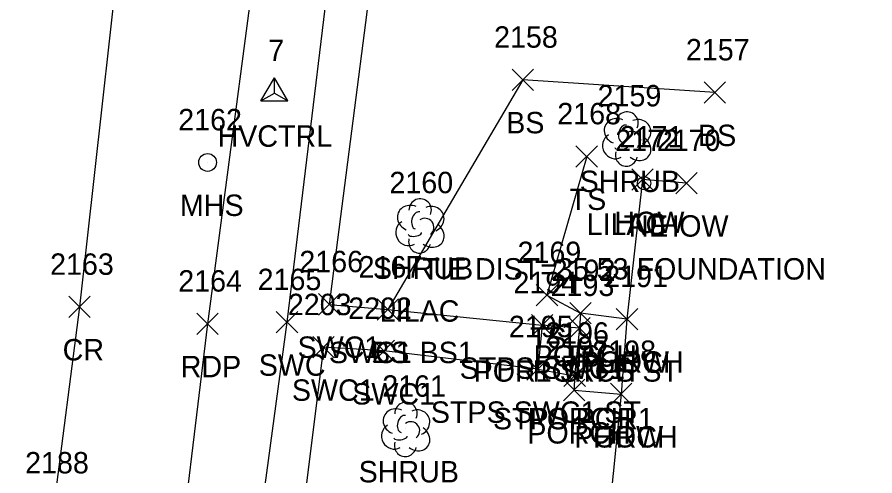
# Model space of a CAD drawing. Extents: x 1651305 to 1654558, y 539481 to 548441.
# Drawn here: x 1654363.2 to 1654443.3, y 544215.2 to 544258.1 of the extents above; entities that cross this region are included whole.
import ezdxf

# ---------------------------------------------------------------- set-up
doc = ezdxf.new("R2010")
doc.units = 0
for name, color, linetype in [('C_A', 7, 'Continuous'), ('C_C', 7, 'Continuous'), ('C_I', 7, 'Continuous'), ('CBP', 7, 'Continuous'), ('CPSM', 7, 'Continuous'), ('L_A', 7, 'Continuous'), ('L_C', 7, 'Continuous'), ('L_I', 7, 'Continuous'), ('L_TIC', 7, 'Continuous'), ('LBC', 7, 'Continuous'), ('LBF', 7, 'Continuous'), ('LELB', 7, 'Continuous'), ('LSH', 7, 'Continuous'), ('P_A', 7, 'Continuous'), ('P_I', 7, 'Continuous'), ('P_TIC', 7, 'Continuous'), ('PET', 7, 'Continuous'), ('PRC', 7, 'Continuous'), ('R_A', 7, 'Continuous'), ('R_I', 7, 'Continuous'), ('R_TIC', 7, 'Continuous'), ('RSW', 7, 'Continuous'), ('U_A', 7, 'Continuous'), ('U_I', 7, 'Continuous'), ('USMH', 7, 'Continuous')]:
    doc.layers.add(name, color=color, linetype=linetype)

msp = doc.modelspace()

# ---------------------------------------------------------------- linework, layer by layer
at = {"layer": 'CBP'}
for radius in [0.625, 0.0833]:
    msp.add_circle((1654421.726, 544242.57), radius, dxfattribs=at)
at = {"layer": 'CPSM'}
for p, q in [((1654385.957, 544250.252), (1654387.207, 544252.417)), ((1654388.457, 544250.252), (1654387.207, 544252.417)), ((1654387.208, 544250.973), (1654387.207, 544252.417)), ((1654385.957, 544250.252), (1654387.208, 544250.973)), ((1654387.208, 544250.973), (1654387.208, 544250.973)), ((1654387.208, 544250.973), (1654388.457, 544250.252)), ((1654385.957, 544250.252), (1654388.457, 544250.252))]:
    msp.add_line(p, q, dxfattribs=at)
at = {"layer": 'L_TIC'}
for points in [[(1654409.411, 544251.227), (1654411.411, 544253.227)], [(1654411.411, 544251.227), (1654409.411, 544253.227)], [(1654427.321, 544250.038), (1654429.321, 544252.038)], [(1654429.321, 544250.038), (1654427.321, 544252.038)], [(1654415.365, 544244.072), (1654417.365, 544246.072)], [(1654417.365, 544244.072), (1654415.365, 544246.072)], [(1654420.566, 544241.909), (1654422.566, 544243.909)], [(1654422.566, 544241.909), (1654420.566, 544243.909)], [(1654424.688, 544241.577), (1654426.688, 544243.577)], [(1654426.688, 544241.577), (1654424.688, 544243.577)], [(1654411.658, 544231.112), (1654413.658, 544233.112)], [(1654413.658, 544231.112), (1654411.658, 544233.112)], [(1654396.808, 544229.762), (1654398.808, 544231.762)], [(1654398.808, 544229.762), (1654396.808, 544231.762)], [(1654414.792, 544229.434), (1654416.792, 544231.434)], [(1654416.792, 544229.434), (1654414.792, 544231.434)], [(1654414.792, 544229.434), (1654416.792, 544231.434)], [(1654416.792, 544229.434), (1654414.792, 544231.434)], [(1654419.127, 544228.866), (1654421.127, 544230.866)], [(1654421.127, 544228.866), (1654419.127, 544230.866)], [(1654419.127, 544228.866), (1654421.127, 544230.866)], [(1654421.127, 544228.866), (1654419.127, 544230.866)], [(1654411.219, 544228.296), (1654413.219, 544230.296)], [(1654413.219, 544228.296), (1654411.219, 544230.296)], [(1654414.695, 544228.032), (1654416.695, 544230.032)], [(1654416.695, 544228.032), (1654414.695, 544230.032)], [(1654414.695, 544228.032), (1654416.695, 544230.032)], [(1654416.695, 544228.032), (1654414.695, 544230.032)], [(1654410.793, 544224.188), (1654412.793, 544226.188)], [(1654412.793, 544224.188), (1654410.793, 544226.188)], [(1654414.241, 544223.579), (1654416.241, 544225.579)], [(1654416.241, 544223.579), (1654414.241, 544225.579)], [(1654414.241, 544223.579), (1654416.241, 544225.579)], [(1654416.241, 544223.579), (1654414.241, 544225.579)], [(1654414.201, 544222.252), (1654416.201, 544224.252)], [(1654416.201, 544222.252), (1654414.201, 544224.252)], [(1654418.583, 544221.879), (1654420.583, 544223.879)], [(1654420.583, 544221.879), (1654418.583, 544223.879)], [(1654418.583, 544221.879), (1654420.583, 544223.879)], [(1654420.583, 544221.879), (1654418.583, 544223.879)]]:
    msp.add_lwpolyline(points, dxfattribs=at)
at = {"layer": 'LBC'}
msp.add_lwpolyline([(1654425.688, 544242.577), (1654421.566, 544242.909), (1654420.127, 544229.866), (1654419.583, 544222.879), (1654418.102, 544208.06), (1654421.917, 544207.562)], dxfattribs=at)
at = {"layer": 'LBF'}
for points in [[(1654420.127, 544229.866), (1654415.792, 544230.434), (1654415.695, 544229.032), (1654415.241, 544224.579), (1654415.201, 544223.252), (1654419.583, 544222.879)], [(1654415.695, 544229.032), (1654412.219, 544229.296), (1654411.793, 544225.188), (1654415.241, 544224.579)]]:
    msp.add_lwpolyline(points, dxfattribs=at)
at = {"layer": 'LELB'}
for points in [[(1654428.321, 544251.038), (1654410.411, 544252.227), (1654397.808, 544230.762)], [(1654416.365, 544245.072), (1654412.658, 544232.112), (1654415.792, 544230.434)]]:
    msp.add_lwpolyline(points, dxfattribs=at)
at = {"layer": 'LSH'}
for p, q in [((1654420.084, 544246.744), (1654420.084, 544246.744)), ((1654420.084, 544246.744), (1654420.084, 544246.744)), ((1654400.775, 544238.634), (1654400.775, 544238.634)), ((1654400.775, 544238.634), (1654400.775, 544238.634)), ((1654399.447, 544219.625), (1654399.447, 544219.625)), ((1654399.447, 544219.625), (1654399.447, 544219.625))]:
    msp.add_line(p, q, dxfattribs=at)
for centre in [(1654420.131, 544248.178), (1654400.822, 544240.068), (1654399.494, 544221.059)]:
    msp.add_arc(centre, 1.047, 335.52715, 180.95627, dxfattribs=at)
for centre, major_axis, ratio, start_param, end_param in [((1654419.292, 544247.411), (1.21, -0.512), 0.895232, 1.570796, 4.712389), ((1654419.875, 544247.202), (-0.208, -0.792), 0.645439, 3.141593, 6.283185), ((1654421.125, 544247.328), (-1.141, -0.483), 0.949671, 1.570796, 4.712389), ((1654420.584, 544246.577), (-0.5, 0.667), 0.989748, 3.141593, 6.283185), ((1654419.001, 544246.035), (0.584, -1.042), 0.959034, 3.141593, 6.283185), ((1654421.084, 544245.911), (-1.09, 0.792), 0.841452, 1.570796, 4.712389), ((1654419.626, 544245.994), (-0.625, -0.083), 0.423636, 0, 3.141593), ((1654420.084, 544245.244), (0.265, 1.061), 0.942809, 1.570796, 4.712389), ((1654399.984, 544239.3), (1.21, -0.512), 0.895232, 1.570796, 4.712389), ((1654401.817, 544239.217), (-1.141, -0.483), 0.949671, 1.570796, 4.712389), ((1654400.567, 544239.092), (-0.208, -0.792), 0.645439, 3.141593, 6.283185), ((1654401.275, 544238.467), (-0.5, 0.667), 0.989748, 3.141593, 6.283185), ((1654399.692, 544237.925), (0.584, -1.042), 0.959034, 3.141593, 6.283185), ((1654401.776, 544237.801), (-1.09, 0.792), 0.841452, 1.570796, 4.712389), ((1654400.317, 544237.884), (-0.625, -0.083), 0.423636, 0, 3.141593), ((1654400.776, 544237.134), (0.265, 1.061), 0.942809, 1.570796, 4.712389), ((1654398.655, 544220.292), (1.21, -0.512), 0.895232, 1.570796, 4.712389), ((1654399.238, 544220.084), (-0.208, -0.792), 0.645439, 3.141593, 6.283185), ((1654400.488, 544220.209), (-1.141, -0.483), 0.949671, 1.570796, 4.712389), ((1654399.947, 544219.459), (-0.5, 0.667), 0.989748, 3.141593, 6.283185), ((1654398.364, 544218.917), (0.584, -1.042), 0.959034, 3.141593, 6.283185), ((1654400.447, 544218.792), (-1.09, 0.792), 0.841452, 1.570796, 4.712389), ((1654398.989, 544218.875), (-0.625, -0.083), 0.423636, 0, 3.141593), ((1654399.447, 544218.125), (0.265, 1.061), 0.942809, 1.570796, 4.712389)]:
    msp.add_ellipse(centre, major_axis=major_axis, ratio=ratio, start_param=start_param, end_param=end_param, dxfattribs=at)
at = {"layer": 'P_TIC'}
for points in [[(1654368.008, 544230.012), (1654370.008, 544232.012)], [(1654370.008, 544230.012), (1654368.008, 544232.012)], [(1654379.974, 544228.445), (1654381.974, 544230.445)], [(1654381.974, 544228.445), (1654379.974, 544230.445)]]:
    msp.add_lwpolyline(points, dxfattribs=at)
at = {"layer": 'PET'}
msp.add_lwpolyline([(1654345.042, 544588.36), (1654350.59, 544607.191), (1654356.582, 544624.309), (1654366.692, 544597.705), (1654378.699, 544565.627), (1654388.798, 544536.019), (1654394.392, 544506.433), (1654399.121, 544481.008), (1654401.125, 544462.893), (1654401.531, 544436.346), (1654401.825, 544421.309), (1654397.366, 544359.696), (1654394.392, 544336.586), (1654391.404, 544308.963), (1654388.941, 544290.736), (1654386.845, 544274.06), (1654380.974, 544229.445), (1654377.749, 544202.908), (1654375.628, 544181.037), (1654372.192, 544149.754), (1654366.612, 544105.723), (1654362.798, 544072.788)], dxfattribs=at)
at = {"layer": 'PRC'}
msp.add_lwpolyline([(1654350.59, 544607.191), (1654355.931, 544592.699), (1654363.685, 544570.628), (1654372.223, 544542.272), (1654380.244, 544505.389), (1654384.95, 544473.916), (1654386.821, 544433.75), (1654385.713, 544395.522), (1654383.86, 544365.997), (1654380.919, 544339.646), (1654377.996, 544311.086), (1654373.889, 544274.842), (1654369.008, 544231.012), (1654366.63, 544212.463), (1654362.444, 544177.974), (1654359.488, 544151.886), (1654354.071, 544107.932), (1654348.42, 544063.008)], dxfattribs=at)
at = {"layer": 'R_TIC'}
for points in [[(1654391.335, 544230.256), (1654393.335, 544232.256)], [(1654393.335, 544230.256), (1654391.335, 544232.256)], [(1654396.808, 544229.762), (1654398.808, 544231.762)], [(1654398.808, 544229.762), (1654396.808, 544231.762)], [(1654387.386, 544228.583), (1654389.386, 544230.583)], [(1654389.386, 544228.583), (1654387.386, 544230.583)], [(1654411.219, 544228.296), (1654413.219, 544230.296)], [(1654413.219, 544228.296), (1654411.219, 544230.296)], [(1654390.804, 544226.245), (1654392.804, 544228.245)], [(1654392.804, 544226.245), (1654390.804, 544228.245)], [(1654396.438, 544225.898), (1654398.438, 544227.898)], [(1654398.438, 544225.898), (1654396.438, 544227.898)], [(1654410.793, 544224.188), (1654412.793, 544226.188)], [(1654412.793, 544224.188), (1654410.793, 544226.188)]]:
    msp.add_lwpolyline(points, dxfattribs=at)
at = {"layer": 'RSW'}
for points in [[(1654407.404, 544661.775), (1654407.293, 544658.868), (1654407.962, 544657.877), (1654443.269, 544654.592), (1654438.81, 544619.894), (1654433.558, 544580.17), (1654430.136, 544553.995), (1654428.025, 544537.281), (1654424.833, 544512.838), (1654419.77, 544473.615), (1654412.659, 544419.662), (1654404.122, 544354.774), (1654402.102, 544339.773), (1654395.487, 544286.058), (1654394.013, 544276.122), (1654388.386, 544229.583), (1654383.891, 544196.376), (1654382.201, 544184.333), (1654378.352, 544149.148), (1654372.361, 544105.495), (1654368.546, 544072.052)], [(1654433.769, 544447.317), (1654420.392, 544448.732), (1654416.298, 544419.47), (1654415.224, 544408.685), (1654412.657, 544388.617), (1654423.018, 544387.519), (1654429.579, 544386.827), (1654429.097, 544382.97), (1654422.687, 544383.714), (1654411.983, 544384.286), (1654408, 544354.107), (1654405.993, 544338.287), (1654403.211, 544318.213), (1654402.851, 544314.962), (1654399.432, 544285.106), (1654398.089, 544275.966), (1654392.335, 544231.256), (1654397.808, 544230.762), (1654412.219, 544229.296)], [(1654411.793, 544225.188), (1654397.438, 544226.898), (1654391.804, 544227.245), (1654387.757, 544194.912), (1654386.473, 544185.092), (1654381.826, 544148.772), (1654376.181, 544105.122), (1654374.342, 544091.887), (1654373.966, 544088.879), (1654371.749, 544071.943)]]:
    msp.add_lwpolyline(points, dxfattribs=at)
at = {"layer": 'USMH'}
for p, q in [((1654380.973, 544244.509), (1654380.973, 544244.509)), ((1654381.806, 544244.509), (1654381.806, 544244.509))]:
    msp.add_line(p, q, dxfattribs=at)
msp.add_circle((1654380.973, 544244.509), 0.833, dxfattribs=at)

# ---------------------------------------------------------------- texts
at = {"layer": 'C_A'}
for s, p in [('HVCTRL', (1654381.901, 544245.973)), ('TIE', (1654419.805, 544237.57))]:
    msp.add_text(s, height=2, dxfattribs=at).set_placement(p)
at = {"layer": 'C_C'}
msp.add_text('TIE DIST=35.53 FOUNDATION', height=2, dxfattribs=at).set_placement((1654401.026, 544233.57))
at = {"layer": 'C_I'}
for s, p in [('7', (1654386.641, 544253.973)), ('2172', (1654419.034, 544245.57))]:
    msp.add_text(s, height=2, dxfattribs=at).set_placement(p)
at = {"layer": 'L_A'}
for s, p in [('BS', (1654408.852, 544247.227)), ('BS', (1654426.762, 544246.038)), ('SHRUB', (1654415.714, 544241.744)), ('TS', (1654414.775, 544240.072)), ('HOW', (1654418.952, 544237.909)), ('HOW', (1654423.074, 544237.577)), ('SHRUB', (1654396.405, 544233.634)), ('TS', (1654411.068, 544227.112)), ('BS', (1654396.249, 544225.762)), ('PORCH', (1654411.414, 544225.434)), ('TS', (1654414.202, 544225.434)), ('PORCH', (1654415.749, 544224.866)), ('HOW', (1654417.513, 544224.866)), ('STPS SWC1', (1654404.503, 544224.296)), ('POR1 STPS ST', (1654405.813, 544224.032)), ('PORCH', (1654411.317, 544224.032)), ('STPS SWC1 ST', (1654401.817, 544220.188)), ('STPS POR1', (1654407.619, 544219.579)), ('PORCH', (1654410.863, 544219.579)), ('PORCH', (1654410.823, 544218.252)), ('PORCH', (1654415.205, 544217.879)), ('HOW', (1654416.969, 544217.879)), ('SHRUB', (1654395.077, 544214.625))]:
    msp.add_text(s, height=2, dxfattribs=at).set_placement(p)
at = {"layer": 'L_C'}
for p in [(1654416.36, 544237.744), (1654397.051, 544229.634)]:
    msp.add_text('LILAC', height=2, dxfattribs=at).set_placement(p)
at = {"layer": 'L_I'}
for s, p in [('2158', (1654407.719, 544255.227)), ('2157', (1654425.628, 544254.038)), ('2159', (1654417.383, 544249.744)), ('2168', (1654413.625, 544248.072)), ('2171', (1654419.441, 544245.909)), ('2170', (1654422.909, 544245.577)), ('2160', (1654397.949, 544241.634)), ('2169', (1654409.91, 544235.112)), ('2167', (1654395.068, 544233.762)), ('2192', (1654413.1, 544233.434)), ('2192', (1654413.1, 544233.434)), ('2191', (1654418.002, 544232.866)), ('2191', (1654418.002, 544232.866)), ('2194', (1654409.526, 544232.296)), ('2193', (1654413.002, 544232.032)), ('2193', (1654413.002, 544232.032)), ('2195', (1654409.1, 544228.188)), ('2196', (1654412.493, 544227.579)), ('2196', (1654412.493, 544227.579)), ('2197', (1654412.508, 544226.252)), ('2198', (1654416.89, 544225.879)), ('2198', (1654416.89, 544225.879)), ('2161', (1654397.274, 544222.625))]:
    msp.add_text(s, height=2, dxfattribs=at).set_placement(p)
at = {"layer": 'P_A'}
for s, p in [('CR', (1654367.441, 544226.012)), ('RDP', (1654378.463, 544224.445))]:
    msp.add_text(s, height=2, dxfattribs=at).set_placement(p)
at = {"layer": 'P_I'}
for s, p in [('2163', (1654366.268, 544234.012)), ('2164', (1654378.235, 544232.445)), ('2188', (1654363.937, 544215.463))]:
    msp.add_text(s, height=2, dxfattribs=at).set_placement(p)
at = {"layer": 'R_A'}
for s, p in [('SWC1', (1654389.374, 544226.256)), ('SWC1 BS1', (1654392.296, 544225.762)), ('SWC', (1654385.748, 544224.583)), ('STPS SWC1', (1654404.503, 544224.296)), ('SWC1', (1654388.843, 544222.245)), ('SWC1', (1654394.478, 544221.898)), ('STPS SWC1 ST', (1654401.817, 544220.188))]:
    msp.add_text(s, height=2, dxfattribs=at).set_placement(p)
at = {"layer": 'R_I'}
for s, p in [('2166', (1654389.54, 544234.256)), ('2167', (1654395.068, 544233.762)), ('2165', (1654385.646, 544232.583)), ('2194', (1654409.526, 544232.296)), ('2203', (1654388.465, 544230.245)), ('2202', (1654394.1, 544229.898)), ('2195', (1654409.1, 544228.188))]:
    msp.add_text(s, height=2, dxfattribs=at).set_placement(p)
at = {"layer": 'U_A'}
msp.add_text('MHS', height=2, dxfattribs=at).set_placement((1654378.391, 544239.509))
at = {"layer": 'U_I'}
msp.add_text('2162', height=2, dxfattribs=at).set_placement((1654378.233, 544247.509))

doc.saveas('drawing.dxf')
